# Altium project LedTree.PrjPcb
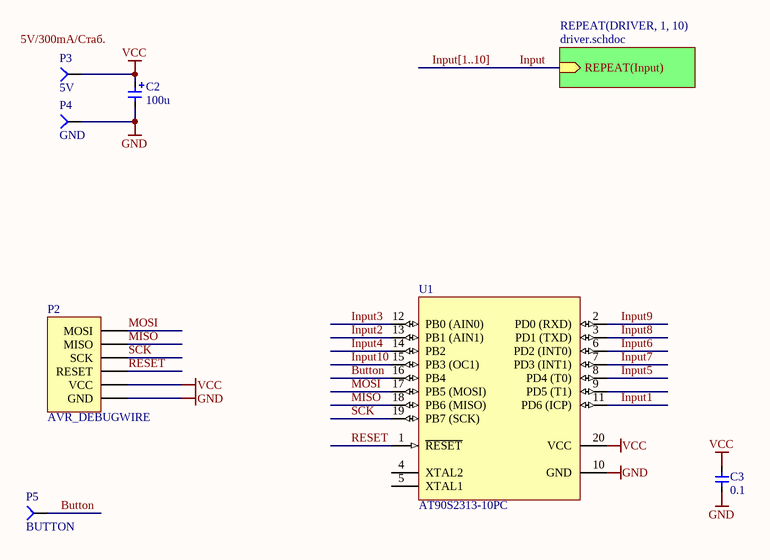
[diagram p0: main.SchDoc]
2 sheets, 57 parts. Net scope: hierarchical (ports join the sheet entries above them; power ports are global).
Board file: LedTree.PcbDoc
Sheets:
  main.SchDoc
    DRIVER1 = driver.SchDoc
    DRIVER2 = driver.SchDoc
    DRIVER3 = driver.SchDoc
    DRIVER4 = driver.SchDoc
    DRIVER5 = driver.SchDoc
    DRIVER6 = driver.SchDoc
    DRIVER7 = driver.SchDoc
    DRIVER8 = driver.SchDoc
    DRIVER9 = driver.SchDoc
    DRIVER10 = driver.SchDoc

## Sheet main.SchDoc
size A4

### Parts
C2  value 100u  [ELECTROLYTIC 2.5*6.5]  (hidden comment: CE_Pinned)
C3  value 0.1  [CK05]  (hidden comment: C_Pinned)
P2  AVR_DEBUGWIRE  [AVR_ISP]
P3  5V  [Pin 2.0x0.5]  (no BOM)
P4  GND  [Pin 2.0x0.5]  (no BOM)
P5  BUTTON  [Pin 2.0x0.5]  (no BOM)
U1  AT90S2313-10PC  [20P3]

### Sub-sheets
REPEAT(DRIVER, 1, 10) = driver.schdoc: REPEAT(Input) (in)

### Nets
GND: C2.2 C3.1 P2.6(GND) P4.1 U1.10(GND)
VCC: C2.1 C3.2 P2.5(VCC) P3.1 U1.20(VCC)
Button: P5.1 U1.16(PB4)
Input1: U1.11(PD6_(ICP))
Input2: U1.13(PB1_(AIN1))
Input3: U1.12(PB0_(AIN0))
Input4: U1.14(PB2)
Input5: U1.8(PD4_(T0))
Input6: U1.6(PD2_(INT0))
Input7: U1.7(PD3_(INT1))
Input8: U1.3(PD1_(TXD))
Input9: U1.2(PD0_(RXD))
Input10: U1.15(PB3_(OC1))
MISO: P2.2(MISO) U1.18(PB6_(MISO))
MOSI: P2.1(MOSI) U1.17(PB5_(MOSI))
RESET: P2.4(RESET) U1.1(~{RESET})
SCK: P2.3(SCK) U1.19(PB7_(SCK))

Not connected (* = marked no-connect by the designer): U1 4(XTAL2) 5(XTAL1) 9(PD5_(T1))

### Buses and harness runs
bus Input[1..10]

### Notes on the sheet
- Labels drawn without touching a wire or pin: 5V/300mA/Стаб.

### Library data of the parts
C2 = CE_Pinned: Polarized Capacitor
C3 = C_Pinned: Capacitor; Manufacturer: Generic Components; Class I: Passive
P2 = AVR_DEBUGWIRE: Header, 6-Pin
P3-P5 = Pin
U1 = AT90S2313-10PC: 8-Bit AVR Microcontroller with 2K Bytes of In-System Programmable Flash Memory

## Sheet driver.SchDoc
size A4
Used 10 times, as channels DRIVER1, DRIVER2, DRIVER3, DRIVER4, DRIVER5, DRIVER6, DRIVER7, DRIVER8, DRIVER9, DRIVER10. Parts and nets are listed once, with the designators drawn on the sheet.
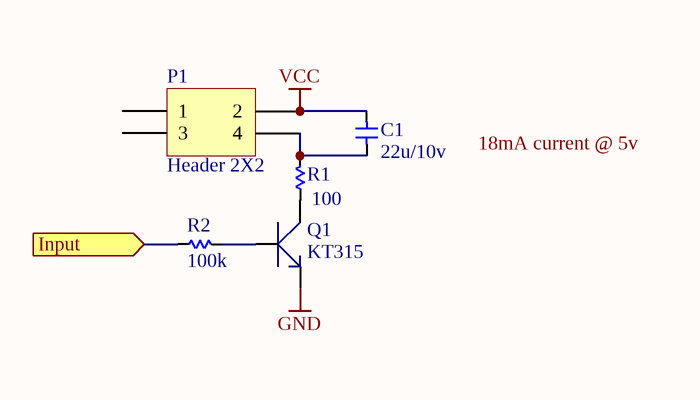
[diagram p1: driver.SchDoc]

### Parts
C1  value 22u/10v  [CK05]  (hidden comment: C_Pinned)
P1  Header 2X2  [HDR2X2]
Q1  KT315  [KT-13]
R1  value 100  [Axial R 10.0x1.6]  (hidden comment: R_Pinned)
R2  value 100k  [Axial R 10.0x1.6]  (hidden comment: R_Pinned)

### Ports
Input (in)

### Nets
GND: Q1.E
VCC: C1.2 P1.2
Input: R2.1 ; port Input
NetC1_1: C1.1 P1.4 R1.2
NetQ1_B: Q1.B R2.2
NetQ1_C: Q1.C R1.1

Not connected (* = marked no-connect by the designer): P1 1 3

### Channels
DRIVER1: designators end in _DRIVER1; ports Input=Input1
DRIVER2: designators end in _DRIVER2; ports Input=Input2
DRIVER3: designators end in _DRIVER3; ports Input=Input3
DRIVER4: designators end in _DRIVER4; ports Input=Input4
DRIVER5: designators end in _DRIVER5; ports Input=Input5
DRIVER6: designators end in _DRIVER6; ports Input=Input6
DRIVER7: designators end in _DRIVER7; ports Input=Input7
DRIVER8: designators end in _DRIVER8; ports Input=Input8
DRIVER9: designators end in _DRIVER9; ports Input=Input9
DRIVER10: designators end in _DRIVER10; ports Input=Input10

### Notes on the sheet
- Labels drawn without touching a wire or pin: 18mA current @ 5v

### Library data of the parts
C1 = C_Pinned: as C3 on sheet main
P1 = Header 2X2: Header, 2-Pin, Dual row
Q1 = KT315: Cool soviet transisto; Type: Transistor
R1 R2 = R_Pinned: Resistor; Manufacturer: Generic Components; Class I: Passive

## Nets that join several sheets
GND: main (5 pins), DRIVER1 (Q1_DRIVER1.E), DRIVER2 (Q1_DRIVER2.E), DRIVER3 (Q1_DRIVER3.E), DRIVER4 (Q1_DRIVER4.E), DRIVER5 (Q1_DRIVER5.E), DRIVER6 (Q1_DRIVER6.E), DRIVER7 (Q1_DRIVER7.E), DRIVER8 (Q1_DRIVER8.E), DRIVER9 (Q1_DRIVER9.E), DRIVER10 (Q1_DRIVER10.E)
VCC: main (5 pins), DRIVER1 (C1_DRIVER1.2 P1_DRIVER1.2), DRIVER2 (C1_DRIVER2.2 P1_DRIVER2.2), DRIVER3 (C1_DRIVER3.2 P1_DRIVER3.2), DRIVER4 (C1_DRIVER4.2 P1_DRIVER4.2), DRIVER5 (C1_DRIVER5.2 P1_DRIVER5.2), DRIVER6 (C1_DRIVER6.2 P1_DRIVER6.2), DRIVER7 (C1_DRIVER7.2 P1_DRIVER7.2), DRIVER8 (C1_DRIVER8.2 P1_DRIVER8.2), DRIVER9 (C1_DRIVER9.2 P1_DRIVER9.2), DRIVER10 (C1_DRIVER10.2 P1_DRIVER10.2)
Input1: main (U1.11), DRIVER1 (R2_DRIVER1.1)
Input2: main (U1.13), DRIVER2 (R2_DRIVER2.1)
Input3: main (U1.12), DRIVER3 (R2_DRIVER3.1)
Input4: main (U1.14), DRIVER4 (R2_DRIVER4.1)
Input5: main (U1.8), DRIVER5 (R2_DRIVER5.1)
Input6: main (U1.6), DRIVER6 (R2_DRIVER6.1)
Input7: main (U1.7), DRIVER7 (R2_DRIVER7.1)
Input8: main (U1.3), DRIVER8 (R2_DRIVER8.1)
Input9: main (U1.2), DRIVER9 (R2_DRIVER9.1)
Input10: main (U1.15), DRIVER10 (R2_DRIVER10.1)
